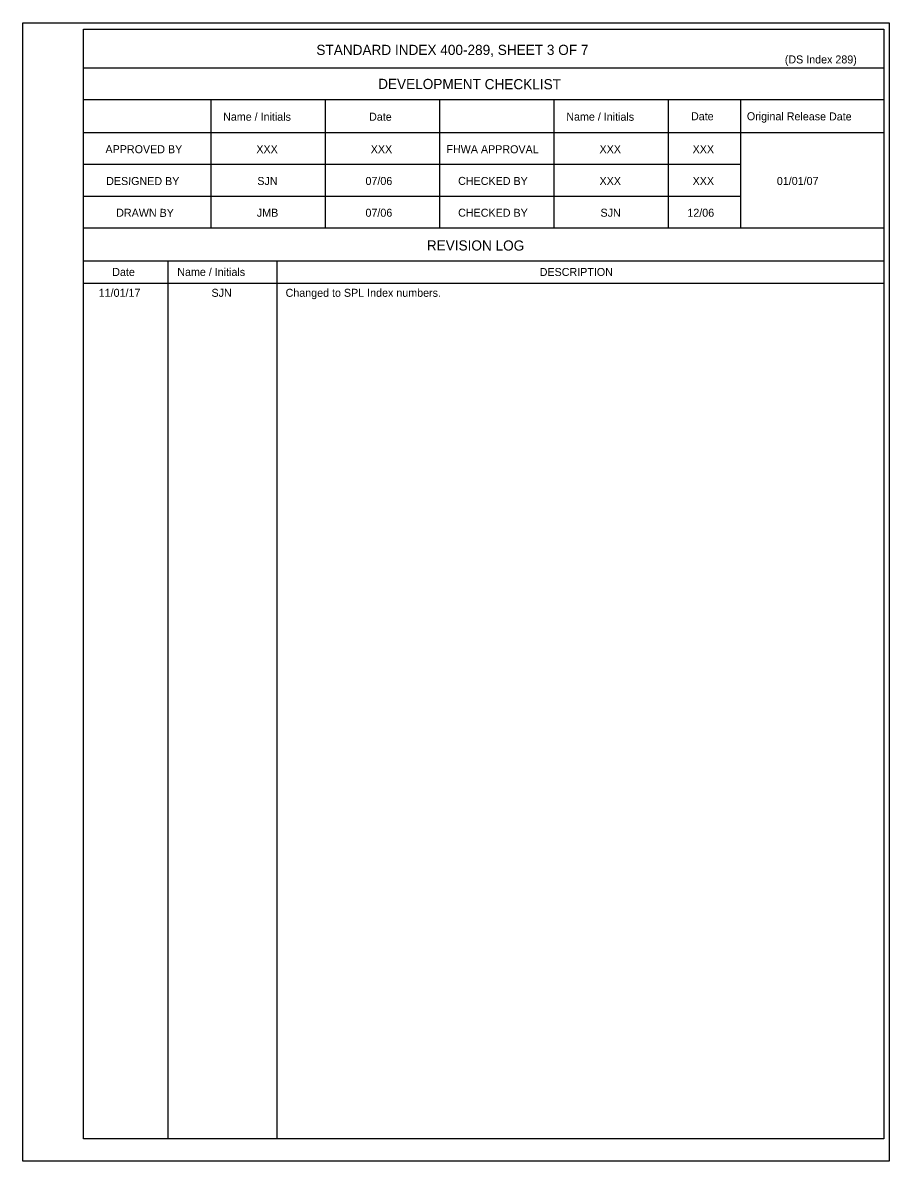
# Model space of a CAD drawing. Extents: x 0 to 221, y -2 to 90.
# Drawn here: x 155.3 to 220.8, y -1.7 to 84.3 of the extents above; entities that cross this region are included whole.
import ezdxf

# ---------------------------------------------------------------- set-up
doc = ezdxf.new("R2010")
doc.units = 0
for name, color, linetype in [('AdhocPoint_dp', 7, 'Continuous'), ('DSSheetNo', 7, 'Continuous'), ('Patterning', 7, 'Continuous'), ('TextMisc', 7, 'Continuous')]:
    doc.layers.add(name, color=color, linetype=linetype)

msp = doc.modelspace()

# ---------------------------------------------------------------- linework, layer by layer
at = {"layer": 'Patterning'}
msp.add_line((155.333, -1.7), (155.333, -1.7), dxfattribs=at)
msp.add_lwpolyline([(155.333, 84.3), (220.772, 84.3), (220.772, -1.7), (155.333, -1.7)], close=True, dxfattribs=at)
at = {"layer": 'TextMisc'}
for p, q in [((220.364, 80.87), (159.924, 80.87)), ((220.364, 78.47), (159.924, 78.47)), ((169.524, 78.47), (169.524, 68.787)), ((178.164, 78.47), (178.164, 68.787)), ((186.804, 78.47), (186.804, 68.787)), ((195.444, 78.47), (195.444, 68.787)), ((204.084, 78.47), (204.084, 68.787)), ((209.529, 78.47), (209.529, 68.787)), ((220.364, 75.987), (159.924, 75.987)), ((209.529, 73.587), (159.924, 73.587)), ((209.529, 71.187), (159.924, 71.187)), ((220.364, 68.787), (159.924, 68.787)), ((220.364, 66.303), (159.924, 66.303)), ((166.285, 66.303), (166.285, -0.016)), ((174.512, 66.303), (174.512, -0.016)), ((220.364, 64.612), (159.924, 64.612))]:
    msp.add_line(p, q, dxfattribs=at)
msp.add_lwpolyline([(159.925, 83.812), (220.364, 83.812), (220.364, -0.016), (159.925, -0.016)], close=True, dxfattribs=at)

# ---------------------------------------------------------------- texts
at = {"layer": 'AdhocPoint_dp'}
for s, height, p in [('STANDARD INDEX 400-289, SHEET 3 OF 7', 0.768, (177.508, 81.868)), ('XXX', 0.6048, (172.974, 74.447)), ('XXX', 0.6048, (181.614, 74.447)), ('XXX', 0.6048, (198.894, 74.447)), ('XXX', 0.6048, (205.924, 74.447)), ('SJN', 0.6048, (173.047, 72.047)), ('07/06', 0.6048, (181.216, 72.047)), ('XXX', 0.6048, (198.894, 72.047)), ('XXX', 0.6048, (205.924, 72.047)), ('01/01/07', 0.6048, (212.285, 72.047)), ('JMB', 0.6048, (173.013, 69.647)), ('07/06', 0.6048, (181.216, 69.647)), ('SJN', 0.6048, (198.967, 69.647)), ('12/06', 0.6048, (205.526, 69.647)), ('DESCRIPTION', 0.6048, (194.375, 65.172)), ('11/01/17', 0.6048, (161.067, 63.598)), ('SJN', 0.6048, (169.588, 63.598)), ('Changed to SPL Index numbers.', 0.6048, (175.182, 63.598))]:
    msp.add_text(s, height=height, dxfattribs=at).set_placement(p)
for s, height, p in [('DEVELOPMENT CHECKLIST', 0.768, (182.171, 79.3)), ('Name / Initials', 0.6048, (170.462, 76.907)), ('Date', 0.6048, (181.486, 76.902)), ('Name / Initials', 0.6048, (196.382, 76.907)), ('Date', 0.6048, (205.801, 76.937)), ('Original Release Date', 0.6048, (210.02, 76.937)), ('APPROVED BY', 0.6048, (161.579, 74.452)), ('FHWA APPROVAL', 0.6048, (187.329, 74.452)), ('DESIGNED BY', 0.6048, (161.63, 72.047)), ('CHECKED BY', 0.6048, (188.214, 72.052)), ('DRAWN BY', 0.6048, (162.388, 69.647)), ('CHECKED BY', 0.6048, (188.214, 69.652)), ('REVISION LOG', 0.768, (185.847, 67.103)), ('Date', 0.6048, (162.091, 65.174)), ('Name / Initials', 0.6048, (167.001, 65.179))]:
    msp.add_text(s, height=height, rotation=359.87563, dxfattribs=at).set_placement(p)
at = {"layer": 'DSSheetNo'}
msp.add_text('(DS Index 289)', height=0.6048, dxfattribs=at).set_placement((212.886, 81.227))

doc.saveas('drawing.dxf')
